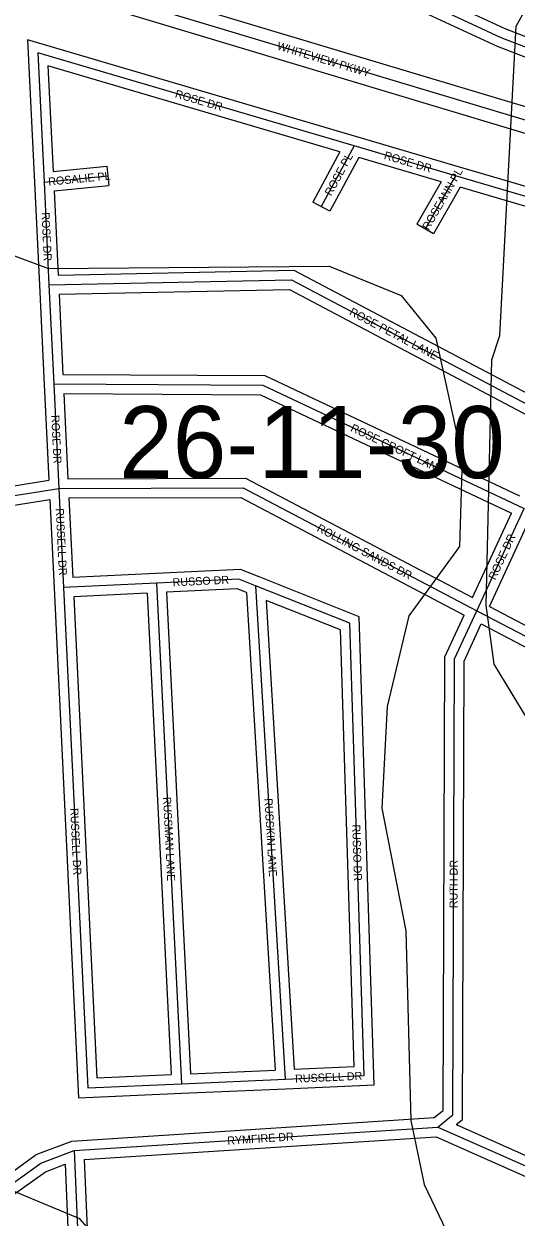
# Model space of a CAD drawing. Extents: x 457167 to 656239, y 1787309 to 1969297.
# Drawn here: x 576898 to 578435, y 1882291 to 1886017 of the extents above; entities that cross this region are included whole.
import ezdxf

# ---------------------------------------------------------------- set-up
doc = ezdxf.new("R2010")
doc.units = 0
for name, color, linetype in [('Level 2', 7, 'Continuous'), ('Level 22', 7, 'Continuous'), ('Level 23', 7, 'Continuous'), ('Level 31', 7, 'Continuous'), ('Level 32', 7, 'Continuous'), ('Level 34', 7, 'Continuous'), ('Level 7', 7, 'Continuous')]:
    doc.layers.add(name, color=color, linetype=linetype)

msp = doc.modelspace()

# ---------------------------------------------------------------- linework, layer by layer
at = {"layer": 'Level 22'}
msp.add_lwpolyline([(577109.898, 1886124.416), (578528.818, 1885697.774), (578629.542, 1885649.562)], dxfattribs=at)
at = {"layer": 'Level 23'}
for points in [[(577146.313, 1886155.236), (578543.298, 1885735.19), (578646.812, 1885685.643)], [(577102.36, 1886084.911), (578514.338, 1885660.358), (578612.273, 1885613.481)]]:
    msp.add_lwpolyline(points, dxfattribs=at)
at = {"layer": 'Level 31'}
for p, q in [((577929.142, 1885636.126), (577826.645, 1885446.887)), ((578246.373, 1885542.73), (577929.142, 1885636.126)), ((576961.039, 1885523.273), (577160.505, 1885542.847)), ((578246.373, 1885542.73), (578150.924, 1885376.746)), ((578553.114, 1885452.63), (578246.373, 1885542.73)), ((576961.039, 1885523.273), (576976.576, 1885202.511)), ((576976.576, 1885202.511), (576991.504, 1884893.021)), ((576991.504, 1884893.021), (577007.03, 1884566.804)), ((576721.646, 1884521.963), (577007.03, 1884566.804)), ((577007.03, 1884566.804), (577022.274, 1884257.314)), ((578312.549, 1884184.761), (578460.484, 1884503.726)), ((577311.751, 1884270.879), (577022.274, 1884257.314)), ((577311.751, 1884270.879), (577389.867, 1882707.791)), ((577621.855, 1884262.584), (577714.345, 1882722.013)), ((578312.549, 1884184.761), (578589.924, 1884039.087)), ((577389.867, 1882707.791), (577714.345, 1882722.013)), ((577714.345, 1882722.013), (577960.569, 1882733.128)), ((578190.528, 1882572.642), (578222.389, 1882598.03)), ((577054.794, 1882499.05), (578190.528, 1882572.642)), ((578190.528, 1882572.642), (579588.2, 1881951.542)), ((577054.794, 1882499.05), (577070.894, 1882141.922))]:
    msp.add_line(p, q, dxfattribs=at)
for points in [[(577879.429, 1886195.146), (577932.779, 1886155.396), (577988.45, 1886160.732), (578387.86, 1885975.162), (578564.242, 1885907.519)], [(577929.142, 1885636.126), (576941.224, 1885926.956), (576961.039, 1885523.273)], [(576976.576, 1885202.511), (577734.242, 1885217.989), (578583.496, 1884769.652)], [(576991.504, 1884893.021), (577643.854, 1884889.087), (578460.484, 1884503.726)], [(577007.03, 1884566.804), (577583.062, 1884568.851), (578312.549, 1884184.761)], [(577621.855, 1884262.584), (577569.099, 1884283.423), (577311.751, 1884270.879)], [(577022.274, 1884257.314), (577097.517, 1882694.96), (577389.867, 1882707.791)], [(577960.569, 1882733.128), (577916.145, 1884145.596), (577621.855, 1884262.584)], [(578222.389, 1882598.03), (578237.365, 1882610.363), (578242.575, 1884034.362), (578312.549, 1884184.761)], [(576716.784, 1882249.242), (576808.929, 1882357.756), (576951.014, 1882459.635), (577054.794, 1882499.05)]]:
    msp.add_lwpolyline(points, dxfattribs=at)
at = {"layer": 'Level 32'}
for p, q in [((578254.845, 1885571.509), (577937.614, 1885664.906)), ((577885.107, 1885617.816), (577800.266, 1885461.175)), ((577943.959, 1885600.49), (577853.025, 1885432.598)), ((578201.396, 1885524.696), (577943.96, 1885600.489)), ((576989.459, 1885556.206), (577157.576, 1885572.704)), ((577157.576, 1885572.704), (577163.436, 1885512.99)), ((578561.569, 1885481.414), (578254.827, 1885571.514)), ((576931.074, 1885521.821), (576946.612, 1885201.059)), ((576992.386, 1885496.205), (577163.436, 1885512.99)), ((578201.396, 1885524.696), (578124.917, 1885391.702)), ((578260.597, 1885507.283), (578176.93, 1885361.791)), ((578508.529, 1885434.457), (578260.597, 1885507.283)), ((576992.386, 1885496.204), (577005.13, 1885233.1)), ((577853.025, 1885432.598), (577800.266, 1885461.175)), ((578176.93, 1885361.791), (578124.917, 1885391.702)), ((576946.611, 1885201.066), (576961.538, 1884891.576)), ((577008.029, 1885173.146), (577020.101, 1884922.849)), ((576961.537, 1884891.595), (576975.784, 1884592.261)), ((577022.976, 1884862.831), (577035.633, 1884596.906)), ((576740.806, 1884555.341), (576975.785, 1884592.261)), ((576751.571, 1884496.295), (576978.709, 1884531.985)), ((576978.709, 1884531.985), (576992.311, 1884255.838)), ((577038.54, 1884536.914), (577050.767, 1884288.681)), ((578298.609, 1884226.006), (578420.729, 1884489.311)), ((578351.781, 1884198.043), (578487.699, 1884491.102)), ((577310.347, 1884300.846), (577050.767, 1884288.681)), ((577283.281, 1884239.511), (577053.685, 1884228.751)), ((577283.281, 1884239.511), (577358.398, 1882736.439)), ((577343.214, 1884242.376), (577418.343, 1882739.068)), ((577593.055, 1884241.704), (577682.572, 1882750.649)), ((577654.632, 1884217.27), (577742.521, 1882753.315)), ((578351.78, 1884198.043), (578603.873, 1884065.647)), ((578326.471, 1884143.563), (578575.975, 1884012.527)), ((577418.342, 1882739.068), (577682.572, 1882750.649)), ((577742.521, 1882753.316), (577929.654, 1882761.763)), ((577391.181, 1882677.819), (577715.66, 1882692.041)), ((577715.699, 1882692.042), (577991.485, 1882704.492)), ((577048.358, 1882528.696), (578179.195, 1882601.971)), ((578179.195, 1882601.971), (578203.694, 1882621.493)), ((578247.741, 1882580.046), (579600.384, 1881978.957)), ((577086.09, 1882471.013), (578185.096, 1882542.226)), ((578185.096, 1882542.226), (579549.984, 1881935.696)), ((577026.693, 1882456.285), (577040.924, 1882140.571)), ((577086.09, 1882471.013), (577099.582, 1882171.718))]:
    msp.add_line(p, q, dxfattribs=at)
for points in [[(577920.014, 1886202.319), (577941.429, 1886186.363), (577993.7, 1886191.374), (578399.565, 1886002.805), (578574.984, 1885935.531)], [(577861.505, 1886171.088), (577924.129, 1886124.428), (577983.201, 1886130.091), (578376.155, 1885947.52), (578553.499, 1885879.508)], [(577937.614, 1885664.906), (576909.19, 1885967.66), (576931.074, 1885521.803)], [(577885.107, 1885617.816), (576973.259, 1885886.251), (576989.459, 1885556.206)], [(577005.13, 1885233.1), (577741.386, 1885248.142), (578569.489, 1884810.97)], [(577008.029, 1885173.146), (577727.098, 1885187.836), (578544.317, 1884756.411)], [(577020.101, 1884922.85), (577650.662, 1884919.047), (578445.948, 1884543.758)], [(577022.976, 1884862.831), (577637.044, 1884859.127), (578420.729, 1884489.311)], [(577035.633, 1884596.906), (577590.426, 1884598.877), (578298.609, 1884226.006)], [(577038.54, 1884536.914), (577575.697, 1884538.823), (578273.301, 1884171.521)], [(577632.877, 1884290.486), (577574.103, 1884313.703), (577310.29, 1884300.844)], [(577991.485, 1882704.492), (577945.512, 1884166.206), (577632.938, 1884290.463)], [(576992.309, 1884255.871), (577068.989, 1882663.678), (577391.182, 1882677.82)], [(577593.055, 1884241.703), (577564.096, 1884253.143), (577343.214, 1884242.376)], [(577053.686, 1884228.751), (577126.045, 1882726.241), (577358.398, 1882736.44)], [(577929.654, 1882761.763), (577886.779, 1884124.986), (577654.632, 1884217.271)], [(578203.694, 1882621.493), (578207.416, 1882624.564), (578212.599, 1884041.052), (578273.301, 1884171.521)], [(578247.741, 1882580.046), (578267.314, 1882596.161), (578272.552, 1884027.672), (578326.471, 1884143.563)], [(576716.883, 1882295.706), (576788.449, 1882379.987), (576936.709, 1882486.294), (577048.358, 1882528.696)], [(576737.409, 1882227.181), (576829.409, 1882335.525), (576965.319, 1882432.976), (577026.693, 1882456.285)]]:
    msp.add_lwpolyline(points, dxfattribs=at)
at = {"layer": 'Level 7'}
for points in [[(579533.288, 1883833.841), (579549.602, 1883483.683), (579390.854, 1883158.735), (579265.714, 1883067.191), (579149.002, 1883075.631), (579040.699, 1883134.112), (578507.894, 1883784.906), (578366.399, 1884018.49), (578341.585, 1884201.925), (578359.066, 1884968.833), (578384.175, 1885043.865), (578435.203, 1886010.809), (578468.613, 1886069.131)], [(576725.548, 1885345.734), (576975.543, 1885253.773), (577850.884, 1885261.157), (578075.859, 1885169.236), (578184.073, 1885035.724), (578267.049, 1884660.485), (578258.422, 1884385.418), (578099.803, 1884168.832), (578032.825, 1883885.465), (578015.789, 1883568.687), (578090.425, 1883185.148), (578106.454, 1882593.234), (578147.937, 1882393.13), (578239.44, 1882201.296)], [(576715.36, 1881584.203), (577088.876, 1882052.476), (577130.714, 1882219.14), (577072.433, 1882285.891), (576772.457, 1882411.263), (576720.306, 1882411.993)]]:
    msp.add_lwpolyline(points, dxfattribs=at)

# ---------------------------------------------------------------- texts
at = {"layer": 'Level 2'}
msp.add_text('26-11-30', height=225, dxfattribs=at).set_placement((577195.719, 1884598.88))
at = {"layer": 'Level 34'}
for s, rotation, p in [('WHITEVIEW PKWY', 343.264817, (577686.815, 1885937.896)), ('ROSE DR', 343.596097, (577368.204, 1885788.229)), ('ROSE DR', 343.5947, (578020.778, 1885596.116)), ('ROSE PL', 61.558075, (577857.834, 1885478.226)), ('ROSALIE PL', 5.604267, (576975.48, 1885512.131)), ('ROSEANN PL', 60.097814, (578162.144, 1885371.187)), ('ROSE DR', 272.772561, (576953.123, 1885428.352)), ('ROSE PETAL LANE', 332.169411, (577912.414, 1885110.453)), ('ROSE DR', 272.724331, (576983.636, 1884795.386)), ('ROSE CROFT LANE', 334.737597, (577916.093, 1884746.798)), ('RUSSELL DR', 272.819272, (576997.614, 1884503.931)), ('ROLLING SANDS DR', 332.2322, (577810.719, 1884434.858)), ('ROSE DR', 65.117358, (578370.026, 1884278.982)), ('RUSSO DR', 2.790278, (577363.174, 1884260.871)), ('RUSSMAN LANE', 272.860275, (577332.619, 1883602.9)), ('RUSSELL DR', 272.756492, (577042.958, 1883568.026)), ('RUSSKIN LANE', 273.434994, (577649.197, 1883598.601)), ('RUSSO DR', 271.800661, (577923.414, 1883516.884)), ('RUTH DR', 89.789608, (578252.227, 1883256.175)), ('RUSSELL DR', 2.584586, (577745.516, 1882710.907)), ('RYMFIRE DR', 3.707128, (577533.894, 1882517.569))]:
    msp.add_text(s, height=25, rotation=rotation, dxfattribs=at).set_placement(p)

doc.saveas('drawing.dxf')
